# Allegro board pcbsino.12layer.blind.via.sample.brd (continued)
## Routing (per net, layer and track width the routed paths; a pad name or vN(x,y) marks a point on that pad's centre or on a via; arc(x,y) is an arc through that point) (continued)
DDR2_CSN0: length 44.8
  TOP w0.114: U10.L2 7.83,14.71
  TOP w0.12: v8(22.27,27.97) U6.P24 ; 7.83,14.71 v8(7.53,15.01) ; U11.L2 v8(7.53,26.21)
  SIG_L5 w0.094: v8(7.53,26.21) 7.53,25.78 7.53,22.7 7.91,22.33 7.91,15.37 7.54,15.01 v8(7.53,15.01)
  SIG_L8 w0.091: v8(7.53,26.21) 7.53,24.79 7.84,24.47 10.89,24.47 11.17,24.75 11.17,26.53 11.27,26.63 11.48,26.63 11.57,26.54 11.57,25.99 11.66,25.9 11.8,25.9 11.89,25.99 11.89,26.54 11.98,26.63 12.12,26.63 12.21,26.54 12.21,25.99 12.3,25.9 12.44,25.9 12.53,25.99 12.53,26.54 12.62,26.63 12.76,26.63 12.85,26.54 12.85,25.99 12.94,25.9 13.08,25.9 13.17,25.99 13.17,26.54 13.26,26.63 15.95,26.63 16.12,26.8 16.12,27.72 16.25,27.86 16.38,27.86 16.72,27.52 16.85,27.52 16.95,27.61 16.95,27.74 16.61,28.08 16.61,28.21 16.7,28.31 16.83,28.31 17.17,27.97 17.3,27.97 17.4,28.06 17.4,28.19 17.06,28.53 17.06,28.66 17.16,28.76 17.29,28.76 17.63,28.42 17.76,28.42 17.85,28.52 17.85,28.65 17.51,28.99 17.51,29.12 17.62,29.22 17.93,29.22 18.02,29.31 18.02,29.49 18.12,29.58 18.25,29.58 18.34,29.49 18.34,29.31 18.44,29.22 18.57,29.22 18.66,29.31 18.66,29.49 18.76,29.58 18.89,29.58 18.98,29.49 18.98,29.31 19.08,29.22 19.21,29.22 19.3,29.31 19.3,29.49 19.4,29.58 19.53,29.58 19.62,29.49 19.62,29.31 19.72,29.22 19.85,29.22 19.94,29.31 19.94,29.49 20.04,29.58 20.17,29.58 20.26,29.49 20.26,29.27 20.59,28.94 22.18,28.94 22.27,28.85 v8(22.27,27.97)
  BOTTOM w0.114: R102.2 7.55,16.43
  BOTTOM w0.12: 7.55,16.43 7.76,16.22 7.76,15.24 v8(7.53,15.01)
DDR2_D0: length 17
  TOP w0.114: U6.E26 21.05,21.17 20.85,20.97
  TOP w0.12: v2(13.94,10.2) U10.D7 ; 20.85,20.97 v2(20.64,20.76)
  INT_L3 w0.091: v2(13.94,10.2) 13.94,10.1 14.02,10.01
  INT_L3 w0.094: v2(20.64,20.76) 20.69,20.71 20.69,20.18 20.07,19.56 19.72,19.56 19.5,19.34 19.5,18.71 18.69,17.89 18.69,12 16.98,10.3 15.51,10.3 14.85,9.64 14.39,9.64 14.02,10.01
DDR2_D1: length 17
  TOP w0.114: v2(14.72,15) 14.7,15 14.4,14.7 14.4,14.67 U10.C2 ; v2(21.48,22.37) 21.87,22.75 U6.G25
  INT_L3 w0.094: v2(14.72,15) 14.72,15.23 15.1,15.61 15.26,15.61 15.35,15.52 15.35,15.01 15.44,14.92 15.56,14.92 15.65,15.01 15.65,15.52 15.74,15.61 16.17,15.61 16.46,15.9 16.46,16.74 16.38,16.83 15.5,16.83 15.41,16.91 15.41,17.07 15.5,17.16 16.38,17.16 16.46,17.25 16.46,17.4 16.38,17.48 16,17.48 15.92,17.57 15.92,17.7 16,17.79 16.38,17.79 16.46,17.88 16.46,19.28 18.51,21.32 18.79,21.32 19.17,21.7 20.82,21.7 v2(21.48,22.37)
DDR2_D2: length 17
  TOP w0.114: v2(15.5,12.84) 15.5,13.38 U10.A3
  TOP w0.12: v2(22.22,21.58) 22.22,21.6 21.87,21.95 U6.F25
  INT_L3 w0.094: v2(15.5,12.84) 15.5,12.93 15.76,13.19 15.76,13.31 15.62,13.46 15.62,13.58 15.7,13.67 15.83,13.67 15.97,13.52 16.09,13.52 16.18,13.61 16.18,13.73 16.04,13.88 16.04,14 16.12,14.09 16.25,14.09 16.39,13.94 16.51,13.94 16.6,14.03 16.6,14.15 16.46,14.3 16.46,14.42 16.54,14.51 16.67,14.51 16.81,14.36 16.93,14.36 17.02,14.45 17.02,14.57 16.88,14.72 16.88,14.84 16.96,14.93 17.09,14.93 17.23,14.78 17.35,14.78 17.47,14.9 17.47,18.73 17.62,18.88 17.62,19.03 17.47,19.18 17.47,19.37 18.73,20.63 19.21,20.63 19.73,21.15 21.31,21.15 21.31,21.15 21.64,21.15 22.06,21.58 v2(22.22,21.58)
DDR2_D3: length 17
  TOP w0.114: v2(22.62,21.91) 22.62,21.93 U6.F24 ; v2(15.49,9.44) U10.B8
  INT_L3 w0.091: v2(22.62,21.91) 22.62,21.55 22.22,21.15 22.11,21.15 21.86,20.9 21.86,20.79
  INT_L3 w0.094: 21.86,20.79 21.86,20.56 21.69,20.38 21.33,20.38 20.36,19.42 20.36,19.04 18.99,17.67 18.99,11.8 17.11,9.92 15.89,9.92 15.49,9.52 v2(15.49,9.44)
DDR2_D4: length 17
  TOP w0.114: U6.F26 21.43,21.61 v2(21.43,21.55) ; v2(15.52,14.2) U10.A2
  INT_L3 w0.091: 20.31,21.43 19.42,21.43 18.95,20.95 18.62,20.95 17.14,19.47 17.14,19.12 17.05,19.03 16.87,19.03 16.78,18.95 16.78,18.83 16.87,18.74 17.05,18.74 17.14,18.65 17.14,18.53 17.05,18.45 16.87,18.45 16.78,18.36 16.78,18.24 16.87,18.15 17.05,18.15 17.14,18.06 17.14,17.94 17.05,17.86 16.87,17.86 16.78,17.77 16.78,17.65 16.87,17.56 17.05,17.56 17.14,17.47 17.14,17.35 17.05,17.27 16.87,17.27 16.78,17.18 16.78,17.06 16.87,16.97 17.05,16.97 17.14,16.89 17.14,16.76 17.05,16.68 16.87,16.68 16.78,16.59 16.78,16.47 16.87,16.38 17.05,16.38 17.14,16.3 17.14,16.17 17.05,16.09 16.87,16.09 16.78,16 16.78,15.88 16.87,15.79 17.05,15.79 17.14,15.71 17.14,15.38 16.98,15.22 16.65,15.22 16.51,15.36 16.38,15.36 16.3,15.28 16.3,15.16 16.44,15.01 16.44,14.89 16.17,14.62 15.25,14.62 15.16,14.53 15.16,14.29 15.25,14.2 v2(15.52,14.2)
  INT_L3 w0.094: 20.31,21.43 21.3,21.43 v2(21.43,21.55)
DDR2_D5: length 17
  TOP w0.114: v2(14.33,13.14) U10.C3
  TOP w0.12: U6.F27 19.87,21.57 19.01,21.57 18.18,20.74 v2(18.18,19.6)
  INT_L3 w0.091: v2(14.33,13.14) 14.24,13.14 14.11,13.01 14.11,12.79 14.8,12.1 15.23,12.1 16.51,13.38 16.63,13.38 16.93,13.08 17.05,13.08 17.13,13.17 17.13,13.29 16.84,13.59 16.84,13.71 16.92,13.79 17.04,13.79 17.34,13.5 17.46,13.5 17.55,13.58 17.55,13.71 17.25,14 17.25,14.12 17.8,14.67 17.8,18.45 18.18,18.83 v2(18.18,19.6)
DDR2_D6: length 17
  TOP w0.114: U10.A7 16.28,10.96 v2(16.32,10.96)
  TOP w0.12: v2(19.87,20.77) U6.E27
  INT_L3 w0.091: v2(16.32,10.96) 16.5,10.78 16.88,10.78 17.05,10.95 17.05,11.07 16.63,11.5 16.63,11.62 16.71,11.71 16.84,11.71 17.26,11.28 17.38,11.28 17.47,11.37 17.47,11.49 17.04,11.91 17.04,12.04 17.13,12.12 17.25,12.12 17.68,11.7 17.8,11.7 17.88,11.78 17.88,11.91 17.46,12.33 17.46,12.45 17.55,12.54 17.67,12.54 18.09,12.11 18.21,12.11 18.41,12.31 18.41,18.1 19.12,18.81 19.12,20.02 v2(19.87,20.77)
DDR2_D7: length 17
  TOP w0.114: U10.C8 14.48,9.95 14.48,9.95 14.67,10.15 v2(14.67,10.2)
  TOP w0.12: v2(18.58,19.95) 18.58,20.49 19.27,21.17 U6.E28
  INT_L3 w0.091: v2(14.67,10.2) 15.64,11.17 15.64,11.29 15.28,11.65 15.28,11.77 15.37,11.86 15.49,11.86 15.85,11.5 15.97,11.5 16.06,11.58 16.06,11.71 15.7,12.07 15.7,12.19 15.78,12.28 15.91,12.28 16.27,11.92 16.39,11.92 16.48,12 16.48,12.12 16.12,12.48 16.12,12.61 16.2,12.69 16.32,12.69 16.58,12.43 16.91,12.43 18.1,13.63 18.1,18.3 18.58,18.78 v2(18.58,19.95)
DDR2_D8: length 20.5
  TOP w0.12: U10.F8 v8(12.33,9.41) ; v8(23.07,23.17) U6.H23
  SIG_L10 w0.091: v8(12.33,9.41) 12.74,10.4 13,10.66 14.8,10.66 18.58,14.44 18.58,17.98 18.8,18.51 18.96,18.57 19.29,19.37 19.23,19.53 19.46,20.1 22.14,22.77 22.34,22.77 22.9,23 v8(23.07,23.17)
DDR2_D9: length 20.5
  TOP w0.114: v8(11.65,11.19) 11.65,10.88 U10.F7
  TOP w0.12: v8(21.47,23.17) U6.H25
  SIG_L10 w0.091: v8(11.65,11.19) 12.01,11.54 14.09,11.54 14.31,11.77 14.31,11.9 14.2,12.01 14.2,12.14 14.33,12.27 14.46,12.27 14.57,12.15 14.7,12.15 15.69,13.14 15.69,13.27 15.54,13.42 15.54,13.55 15.67,13.68 15.8,13.68 15.95,13.53 16.08,13.53 16.21,13.66 16.21,13.79 16.06,13.94 16.06,14.07 16.19,14.2 16.31,14.2 16.46,14.05 16.59,14.05 16.86,14.31 16.86,19.14 20.52,22.8 21.09,22.8 v8(21.47,23.17)
DDR2_D10: length 20.5
  TOP w0.12: v8(22.27,23.17) U6.H24 ; U10.H8 v8(10.73,9.41)
  SIG_L10 w0.091: v8(22.27,23.17) 21.9,22.99 19.23,20.32 18.18,17.78 18.18,15.76 17.41,13.9 14.47,10.96 12.98,10.96 12.71,10.85 12.19,10.5 10.86,9.41 v8(10.73,9.41)
DDR2_D11: length 20.5
  TOP w0.114: 10.74,14.21 U10.G2
  TOP w0.12: v8(10.73,14.21) 10.74,14.21 ; v8(20.67,23.17) U6.H26
  SIG_L10 w0.091: v8(20.67,23.17) 20.43,23.17 16.45,19.19 16.45,15.41 16.07,15.02 15.69,15.02 15.34,14.67 15.34,14.01 13.31,11.99 11,11.99 10.58,12.41 10.58,14.03 10.7,14.15 10.7,14.17 v8(10.73,14.21)
DDR2_D12: length 20.5
  TOP w0.12: v8(20.67,22.37) U6.G26 ; U10.H7 v8(9.93,10.21)
  SIG_L10 w0.091: v8(9.93,10.21) 11.2,10.21 12.23,11.24 14.24,11.24 17.19,14.19 17.77,15.86 17.77,17.22 17.68,17.31 17.58,17.31 17.49,17.4 17.49,17.58 17.58,17.67 17.68,17.67 17.77,17.77 17.77,17.95 17.68,18.04 17.58,18.04 17.49,18.13 17.49,18.31 17.58,18.41 17.68,18.41 17.77,18.5 17.77,18.68 17.68,18.77 17.61,18.77 17.52,18.86 17.52,19.05 17.61,19.14 17.68,19.14 17.77,19.23 17.77,19.48 v8(20.67,22.37)
DDR2_D13: length 20.5
  TOP w0.114: v8(11.53,15.01) U10.F2
  TOP w0.12: v8(21.47,23.97) U6.J25
  SIG_L10 w0.091: v8(21.47,23.97) 20.79,24.65 17.11,24.65 16.2,23.74 15.7,23.74 15.58,23.86 15.41,23.86 15.28,23.74 15.11,23.74 14.99,23.86 14.82,23.86 14.69,23.74 14.53,23.74 14.4,23.86 14.23,23.86 14.1,23.74 13.94,23.74 13.81,23.86 13.64,23.86 13.51,23.74 13.35,23.74 13.22,23.86 13.05,23.86 12.93,23.74 12.44,23.74 11.9,23.2 11.9,17.36 11.73,17.18 11.73,15.2 v8(11.53,15.01)
DDR2_D14: length 20.5
  TOP w0.114: U10.E3 12.73,13.81 v8(12.33,14.2)
  TOP w0.12: v8(20.67,23.97) U6.J26
  SIG_L10 w0.091: v8(12.33,14.2) 12.79,14.67 12.79,16.14 12.7,16.23 12.7,22.81 13.25,23.36 13.46,23.36 13.55,23.27 13.55,23.11 13.64,23.03 13.76,23.03 13.84,23.11 13.84,23.27 13.93,23.36 14.05,23.36 14.14,23.27 14.14,23.11 14.22,23.03 14.35,23.03 14.43,23.11 14.43,23.27 14.52,23.36 14.64,23.36 14.73,23.27 14.73,23.11 14.81,23.03 14.94,23.03 15.02,23.11 15.02,23.27 15.11,23.36 15.23,23.36 15.32,23.27 15.32,23.11 15.4,23.03 16.04,23.03 17.39,24.37 20.27,24.37 v8(20.67,23.97)
DDR2_D15: length 20.5
  TOP w0.12: v8(22.27,23.97) U6.J24 ; v8(11.17,12.61) 11.07,12.61 10.67,13.01 U10.H3
  SIG_L10 w0.091: v8(11.17,12.61) 11.45,12.33 13,12.33 14.11,13.45 14.11,14.36 15.59,15.84 15.59,18.81 15.69,19.07 20.17,23.55 21.84,23.55 v8(22.27,23.97)
DDR2_D16: length 14.8
  TOP w0.114: U11.C2 v8(14.73,26.21)
  TOP w0.12: v8(23.87,25.57) U6.L22
  SIG_L5 w0.091: v8(23.87,25.57) 23.87,25.84 22.98,26.73 22.04,26.73 21.68,27.09 16.86,27.09 16.22,27.72 13.83,27.72 13.53,27.42 13.53,26.7 13.62,26.61 14.33,26.61 v8(14.73,26.21)
DDR2_D17: length 14.8
  TOP w0.12: U11.C8 v8(14.73,20.61) ; v8(25.47,24.77) U6.K20
  SIG_L5 w0.091: v8(25.47,24.77) 25.04,24.35 24.51,24.35 24.29,24.13 24.29,23.81 24.04,23.55 23.68,23.55 23.49,23.36 23.49,23.07 23.18,22.75 23.01,22.75 22.64,22.39 22.64,22.22 22.42,22 22.26,22 21.96,21.7 20.87,21.7 20.15,20.98 19.28,20.98 19.11,20.82 18.98,20.82 18.82,20.98 18.69,20.98 18.52,20.82 18.4,20.82 18.23,20.98 18.1,20.98 17.93,20.82 17.81,20.82 17.64,20.98 17.51,20.98 17.34,20.82 17.22,20.82 17.05,20.98 16.92,20.98 16.75,20.82 16.63,20.82 16.46,20.98 15.11,20.98 v8(14.73,20.61)
DDR2_D18: length 14.7
  TOP w0.114: v8(13.2,22.44) 13.53,22.11 U11.D7
  TOP w0.12: v8(24.67,24.77) U6.K21
  SIG_L5 w0.091: v8(13.2,22.44) 14.04,21.6 20.21,21.6 20.6,22 21.29,22 22.09,22.8 22.42,22.8 22.64,23.02 22.64,23.28 22.91,23.55 23.18,23.55 23.44,23.82 23.44,24.02 23.82,24.4 24.02,24.4 24.4,24.77 v8(24.67,24.77)
DDR2_D19: length 14.8
  TOP w0.114: U11.A2 15.93,25.81 v8(15.53,25.41)
  TOP w0.12: v8(23.07,25.57) U6.L23
  SIG_L5 w0.091: v8(15.53,25.41) 15.34,25.41 15.11,25.64 15.11,27.33 15.22,27.45 15.99,27.45 16.65,26.78 20.53,26.78 20.61,26.7 20.61,26.44 20.7,26.35 20.82,26.35 20.91,26.44 20.91,26.7 21,26.78 21.21,26.78 21.3,26.7 21.3,26.06 21.38,25.97 21.5,25.97 21.59,26.06 21.59,26.34 21.68,26.43 21.8,26.43 21.89,26.34 21.89,26.06 21.97,25.97 22.09,25.97 22.18,26.06 22.18,26.34 22.27,26.43 22.39,26.43 22.47,26.34 22.47,26.06 22.56,25.97 22.95,25.97 23.07,25.86 v8(23.07,25.57)
DDR2_D20: length 14.8
  TOP w0.114: U11.C3 v8(13.93,25.41)
  TOP w0.12: v8(22.27,25.57) U6.L24
  SIG_L5 w0.091: v8(22.27,25.57) 21.02,25.57 20.65,25.94 20.52,25.94 20.26,25.68 20.14,25.68 20.06,25.77 20.06,25.89 20.32,26.15 20.32,26.27 20.13,26.45 19.54,26.45 19.46,26.37 19.46,26.29 19.37,26.2 19.25,26.2 19.16,26.29 19.16,26.37 19.07,26.45 18.95,26.45 18.87,26.37 18.87,26.29 18.78,26.2 18.66,26.2 18.57,26.29 18.57,26.37 18.49,26.45 18.36,26.45 18.28,26.37 18.28,26.29 18.19,26.2 18.07,26.2 17.98,26.29 17.98,26.37 17.9,26.45 17.77,26.45 17.69,26.37 17.69,26.29 17.6,26.2 17.48,26.2 17.39,26.29 17.39,26.37 17.31,26.45 17.18,26.45 17.1,26.37 17.1,26.29 16.82,26.01 16.46,26.01 16.37,26.1 16.37,26.61 16.27,26.71 16.07,26.71 15.97,26.61 15.97,25.16 15.77,24.96 14,24.96 13.91,25.05 13.91,25.39 v8(13.93,25.41)
DDR2_D21: length 14.8
  TOP w0.114: U11.A7 16.15,21.81 v8(16.76,22.42)
  TOP w0.12: v8(23.07,23.97) U6.J23
  SIG_L5 w0.091: v8(16.76,22.42) 17.04,22.7 17.26,22.7 17.35,22.61 17.35,22.15 17.44,22.06 17.56,22.06 17.64,22.15 17.64,22.69 17.73,22.77 17.85,22.77 17.94,22.69 17.94,22.15 18.02,22.06 18.15,22.06 18.23,22.15 18.23,22.69 18.32,22.77 18.44,22.77 18.53,22.69 18.53,22.15 18.61,22.06 18.74,22.06 18.82,22.15 18.82,22.69 18.91,22.77 19.03,22.77 19.12,22.69 19.12,22.15 19.2,22.06 19.33,22.06 19.41,22.15 19.41,22.69 19.5,22.77 19.62,22.77 19.71,22.69 19.71,22.15 19.79,22.06 19.91,22.06 20,22.15 20,22.69 20.09,22.77 21.61,22.77 21.89,23.06 21.89,23.33 22.11,23.55 22.39,23.55 22.68,23.84 22.93,23.84 v8(23.07,23.97)
DDR2_D22: length 14.8
  TOP w0.114: 15.89,25.01 U11.A3
  TOP w0.12: v8(23.87,24.77) U6.K22 ; 15.89,25.01 15.41,24.52 v8(15.41,24.51)
  SIG_L5 w0.091: v8(15.41,24.51) 15.86,24.51 17.2,25.86 19.1,25.86 19.8,25.16 19.95,25.16 20.03,25.07 20.03,24.53 20.12,24.45 20.24,24.45 20.33,24.53 20.33,25.07 20.41,25.16 20.54,25.16 20.62,25.07 20.62,24.53 20.71,24.45 20.83,24.45 20.92,24.53 20.92,25.07 21,25.16 21.12,25.16 21.21,25.07 21.21,24.53 21.3,24.45 21.42,24.45 21.51,24.53 21.51,25.07 21.59,25.16 21.83,25.16 21.92,25.07 21.92,24.99 22,24.91 22.13,24.91 22.21,24.99 22.21,25.07 22.3,25.16 23.54,25.16 23.87,24.83 v8(23.87,24.77)
DDR2_D23: length 14.8
  TOP w0.114: U11.B8 v8(15.53,20.61)
  TOP w0.12: v8(25.47,23.97) U6.J20
  SIG_L5 w0.091: v8(25.47,23.97) 25.47,23.89 25.13,23.55 24.51,23.55 24.25,23.28 24.25,22.9 24.1,22.75 23.71,22.75 23.49,22.53 23.49,22.19 23.3,22 22.89,22 22.29,21.4 21.05,21.4 20.08,20.43 19.5,20.43 19.24,20.18 18.85,20.18 18.77,20.27 18.77,20.32 18.68,20.41 18.56,20.41 18.47,20.32 18.47,20.27 18.39,20.18 18.26,20.18 18.18,20.27 18.18,20.32 18.09,20.41 17.97,20.41 17.88,20.32 17.88,20.27 17.8,20.18 17.67,20.18 17.59,20.27 17.59,20.32 17.5,20.41 17.38,20.41 17.29,20.32 17.29,20.27 17.21,20.18 17.09,20.18 17,20.27 17,20.32 16.91,20.41 16.79,20.41 16.7,20.32 16.7,20.27 16.62,20.18 16.5,20.18 16.41,20.27 16.41,20.32 16.32,20.41 16.2,20.41 16.12,20.32 16.12,20.27 16.03,20.18 15.62,20.18 15.53,20.27 v8(15.53,20.61)
DDR2_D24: length 15.9
  TOP w0.114: U11.F7 11.96,22.67 v2(11.98,22.7)
  INT_L3 w0.091: v2(11.98,22.7) 11.26,22.7 11.17,22.6 11.17,22.46 11.25,22.38 11.51,22.38 11.6,22.29 11.6,22.17 11.51,22.08 11.25,22.08 11.17,21.99 11.17,21.19 11.26,21.1 11.5,21.1 11.65,21.25 11.65,21.65 12.43,22.43 12.43,22.88 12.52,22.96 15.66,22.96 16.52,23.82 16.67,23.97 16.67,24.67 17.46,25.46 19.47,25.46 19.98,25.97 v2(20.26,25.97)
DDR2_D25: length 15.9
  TOP w0.114: U11.H8 v2(10.74,20.61)
  TOP w0.12: v2(20.69,25.64) 21.02,25.97 U6.L26
  INT_L3 w0.091: v2(20.69,25.64) 20.18,25.64 19.19,24.65 17.39,24.65 16.96,24.22 16.96,23.61 15.33,21.98 12.41,21.98 11.96,21.53 11.96,21.14 11.95,21.14 11.95,19.67 11.71,19.43 11.33,19.43 11.12,19.65 11.12,20.23 v2(10.74,20.61)
DDR2_D26: length 15.9
  TOP w0.114: v2(21.4,25.54) 21.4,25.59 21.79,25.97 U6.L25 ; v2(12.33,20.61) U11.F8
  INT_L3 w0.091: v2(12.33,20.61) 12.33,21.5 12.54,21.7 13.62,21.7 13.71,21.62 13.71,21.51 13.79,21.43 13.92,21.43 14,21.51 14,21.62 14.09,21.7 14.21,21.7 14.3,21.62 14.3,21.51 14.38,21.43 14.51,21.43 14.59,21.51 14.59,21.62 14.68,21.7 14.8,21.7 14.89,21.62 14.89,21.51 14.97,21.43 15.09,21.43 15.18,21.51 15.18,21.62 15.27,21.7 15.42,21.7 15.64,21.93 15.76,21.93 16.05,21.63 16.18,21.63 16.26,21.72 16.26,21.84 15.97,22.13 15.97,22.26 17.24,23.53 17.24,24.12 17.49,24.37 19.32,24.37 20.03,25.08 20.18,25.08 20.26,25 20.26,24.77 20.35,24.68 20.47,24.68 20.56,24.77 20.56,25 20.65,25.08 20.95,25.08 v2(21.4,25.54)
DDR2_D27: length 15.9
  TOP w0.114: v2(17.62,25.83) 17.62,25.81 17.74,25.69 17.9,25.69 18.18,25.97 19.07,25.97 U6.L28 ; U11.H7 10.06,22.06 v2(10.05,22.29)
  INT_L3 w0.091: v2(10.05,22.29) 10.05,23.15 10.15,23.25 10.34,23.25 10.43,23.16 10.43,21.97 10.52,21.88 10.66,21.88 10.76,21.98 10.76,23.17 10.85,23.25 11.03,23.25 11.19,23.1 11.33,23.1 11.48,23.25 11.62,23.25 11.78,23.1 11.92,23.1 12.07,23.25 13,23.25 13.15,23.41 13.29,23.41 13.44,23.25 13.59,23.25 13.74,23.41 13.88,23.41 14.03,23.25 14.17,23.25 14.33,23.41 14.47,23.41 14.62,23.25 14.76,23.25 14.92,23.41 15.06,23.41 15.21,23.25 15.59,23.25 16.41,24.08 16.41,24.79 17.45,25.83 v2(17.62,25.83)
DDR2_D28: length 15.9
  TOP w0.114: U11.H3 v2(10.7,25.45) ; v2(23.43,26.72) 23.43,26.74 U6.M23
  INT_L3 w0.091: v2(23.43,26.72) 22.99,26.72 22.69,27.02 22.69,27.3 22.39,27.6 18.74,27.6 18.33,28 11.98,28 11.12,27.14 11.12,25.87 10.7,25.45 v2(10.7,25.45)
DDR2_D29: length 15.9
  TOP w0.114: v2(23.03,26.33) 22.67,26.69 U6.M24 ; v2(11.52,25.44) 11.5,25.44 U11.G2
  INT_L3 w0.091: v2(11.52,25.44) 11.65,25.44 11.8,25.59 11.8,26.17 11.72,26.25 11.51,26.25 11.42,26.34 11.42,26.46 11.51,26.55 11.84,26.55 11.93,26.63 11.93,27.55 12.11,27.73 18.15,27.73 18.54,27.34 21.53,27.34 22.14,26.73 22.47,26.73 22.88,26.33 v2(23.03,26.33)
DDR2_D30: length 15.9
  TOP w0.114: U11.F2 v2(12.29,26.15) ; v2(22.27,26.33) 22.27,26.37 U6.M25
  INT_L3 w0.091: v2(12.29,26.15) 12.46,26.15 12.74,26.43 12.74,27.19 13.02,27.47 14.16,27.47 14.32,27.32 14.32,26.68 14.42,26.58 15.03,26.58 15.13,26.69 15.13,27.37 15.23,27.47 15.98,27.47 16.07,27.38 16.07,27.15 16.16,27.06 16.28,27.06 16.37,27.15 16.37,27.38 16.45,27.47 16.57,27.47 16.66,27.38 16.66,27.15 16.75,27.06 16.87,27.06 16.95,27.15 16.95,27.38 17.04,27.47 17.16,27.47 17.25,27.38 17.25,27.15 17.34,27.06 17.46,27.06 17.54,27.15 17.54,27.38 17.63,27.47 18,27.47 18.41,27.06 21.35,27.06 22.09,26.33 v2(22.27,26.33)
DDR2_D31: length 15.9
  TOP w0.114: U11.E3 v2(12.36,25.38) ; U6.M26 21.48,26.36 v2(21.48,26.33)
  INT_L3 w0.091: v2(21.48,26.33) 21.48,26.51 21.2,26.78 21.02,26.78 20.94,26.7 20.94,26.11 20.85,26.02 20.73,26.02 20.64,26.11 20.64,26.7 20.56,26.78 16.88,26.78 15.92,25.82 15.41,25.82 15.15,25.56 15.15,24.8 15,24.65 14.7,24.65 14.62,24.73 14.62,24.96 14.34,25.24 14.34,25.72 14.24,25.82 13.55,25.82 13.47,25.91 13.47,26.52 13.38,26.61 13.26,26.61 13.17,26.52 13.17,25.91 13.09,25.82 12.45,25.82 12.36,25.73 v2(12.36,25.38)
DDR2_DQM0: length 17
  TOP w0.114: v2(13.83,13.3) 13.53,13.6 U10.D3
  TOP w0.12: U6.F28 19.4,21.91 18.66,21.91 v2(18.44,21.69)
  INT_L3 w0.091: v2(13.83,13.3) 13.66,13.48 13.66,13.75 13.74,13.84 13.95,13.84 14.04,13.92 14.04,14.05 13.95,14.13 13.74,14.13 13.66,14.22 13.66,14.34 13.74,14.43 13.95,14.43 14.04,14.51 14.04,14.64 13.95,14.72 13.74,14.72 13.66,14.81 13.66,14.93 13.74,15.02 13.95,15.02 14.04,15.1 14.04,15.23 13.95,15.31 13.74,15.31 13.66,15.4 13.66,15.52 13.74,15.61 13.95,15.61 14.04,15.69 14.04,15.81 13.95,15.9 13.74,15.9 13.66,15.99 13.66,16.27 13.83,16.44 13.95,16.44 14.11,16.28 14.23,16.28 14.31,16.37 14.31,16.49 14.16,16.65 14.16,16.77 14.24,16.86 14.37,16.86 14.52,16.7 14.65,16.7 14.73,16.78 14.73,16.91 14.57,17.06 14.57,17.19 14.66,17.27 14.78,17.27 14.94,17.12 15.06,17.12 15.15,17.2 15.15,17.32 14.99,17.48 14.99,17.6 15.08,17.69 15.2,17.69 15.36,17.53 15.48,17.53 15.57,17.62 15.57,17.74 15.41,17.9 15.41,18.02 15.49,18.11 15.8,18.11 16.1,18.4 16.1,19.34 v2(18.44,21.69)
DDR2_DQM1: length 20.5
  TOP w0.12: v8(22.27,22.37) U6.G24 ; U10.E7 v8(13.13,10.21)
  SIG_L10 w0.091: v8(13.13,10.21) 15.16,10.21 15.4,10.44 15.53,10.44 15.61,10.35 15.74,10.35 15.87,10.48 15.87,10.61 15.79,10.7 15.79,10.83 15.92,10.96 16.05,10.96 16.13,10.87 16.26,10.87 16.39,11 16.39,11.13 16.3,11.22 16.3,11.35 16.43,11.48 16.56,11.48 16.65,11.39 16.78,11.39 16.91,11.52 16.91,11.65 16.82,11.73 16.82,11.86 16.95,11.99 17.08,11.99 17.17,11.91 17.3,11.91 17.43,12.04 17.43,12.17 17.34,12.25 17.34,12.38 17.47,12.51 17.6,12.51 17.68,12.42 17.81,12.42 17.94,12.55 17.94,12.68 17.86,12.77 17.86,12.9 18.08,13.12 18.46,13.12 19.02,13.68 19.02,17.64 20.67,19.29 20.67,20.77 v8(22.27,22.37)
DDR2_DQM2: length 14.8
  TOP w0.12: v8(23.07,24.77) U6.K23 ; U11.D3 v8(13.13,25.41)
  SIG_L5 w0.091: v8(23.07,24.77) 22.74,24.45 22.14,24.45 21.86,24.17 21.86,23.83 21.58,23.55 19.78,23.55 19.5,23.82 19.5,25.08 19.04,25.54 17.37,25.54 15.92,24.09 13.96,24.09 13.13,24.93 v8(13.13,25.41)
DDR2_DQM3: length 15.9
  TOP w0.114: U11.E7 12.73,21.79 v2(13.12,21.4) ; U6.M22 v2(23.89,26.35)
  INT_L3 w0.091: 13.14,21.4 13.14,21.18 13.28,21.04 13.5,21.04 13.58,20.96 13.58,20.77 13.67,20.69 13.79,20.69 13.88,20.77 13.88,20.96 13.96,21.04 16.1,21.04 17.37,22.31 17.37,22.8 17.95,23.38 19.14,23.38 19.5,23.74 19.5,24.09 19.5,24.14 19.79,24.42 21.38,24.42 22.15,25.2 23.22,25.2 23.44,25.42 23.44,26.18 23.61,26.35 v2(23.89,26.35) ; 13.14,21.4 v2(13.12,21.4) ; 13.14,21.4 13.13,21.41
DDR2_DQS0_N: length 17
  TOP w0.102: U10.B7 14.9,10.83 v2(14.9,11.11)
  TOP w0.114: v2(20.22,22.8) 20.24,22.8 U6.G27
  INT_L3 w0.089: v2(20.22,22.8) 20.08,22.8 19.99,22.71 20,22.57 20,22.28 19.77,22.05 18.1,22.05 15.6,19.55 15.6,18.79 13.26,16.45 13.26,13.09 14.8,11.56 14.8,11.21 v2(14.9,11.11)
DDR2_DQS0_P: length 17
  TOP w0.102: U10.C7 14.58,10.86 14.58,11 v2(14.5,11.09)
  TOP w0.114: U6.G28 v2(19.52,22.77)
  INT_L3 w0.089: v2(19.52,22.77) 19.66,22.78 19.75,22.69 19.76,22.57 19.76,22.38 19.67,22.29 18,22.29 15.36,19.65 15.36,18.89 13.02,16.55 13.02,12.99 14.56,11.46 14.56,11.2 v2(14.5,11.09)
DDR2_DQS1_N: length 20.5
  TOP w0.102: v8(18.46,23.79) 18.31,23.79 18.13,23.61 18.13,23.36 18.26,23.23 18.97,23.23 19.31,23.57 U6.H28 ; v8(11.63,13.31) U10.G3
  SIG_L10 w0.089: v8(11.63,13.31) 11.74,13.31 12.31,12.74 12.73,12.74 13.47,13.48 13.47,15.15 13.96,15.65 13.96,16.31 13.73,16.54 13.56,16.54 13.47,16.63 13.47,16.8 13.56,16.89 13.73,16.89 13.96,17.12 13.96,17.58 13.47,18.07 13.47,19 14.04,19.57 14.04,21.24 14.32,21.51 17.36,21.51 18.22,22.37 18.22,23.53 v8(18.46,23.79)
DDR2_DQS1_P: length 20.5
  TOP w0.102: v8(12.29,13.32) 12.29,13.45 U10.F3 ; v8(17.77,23.76) 17.87,23.66 17.87,23.25 18.15,22.97 19.07,22.97 19.29,23.19 19.71,23.19 20.1,23.57 U6.H27
  SIG_L10 w0.089: v8(12.29,13.32) 12.31,13.3 12.31,13.08 12.41,12.98 12.63,12.98 13.23,13.58 13.23,15.25 13.72,15.75 13.72,16.21 13.63,16.3 13.46,16.3 13.23,16.53 13.23,16.9 13.46,17.13 13.63,17.13 13.72,17.22 13.72,17.48 13.23,17.97 13.23,19.1 13.8,19.67 13.8,21.34 14.22,21.76 17.26,21.76 17.97,22.47 17.97,23.57 v8(17.77,23.76)
DDR2_DQS2_N: length 14.7
  TOP w0.102: v8(18.61,25.08) 18.61,24.47 18.71,24.37 19.02,24.37 19.1,24.45 19.1,25.23 19.18,25.31 19.33,25.31 19.42,25.22 19.42,25.22 U6.K28 ; v8(15.09,22.4) 14.95,22.4 14.83,22.28 14.83,21.99 15,21.81 U11.B7
  SIG_L5 w0.089: v8(18.61,25.08) 18.41,24.89 18.41,24.66 18.09,24.33 17.19,24.33 17.1,24.24 17.1,23.75 16.87,23.52 16.34,23.52 16.25,23.44 16.25,22.62 16.02,22.39 15.7,22.39 15.48,22.62 15.48,23.44 15.39,23.52 13.17,23.52 13.09,23.43 13.09,23.23 13.17,23.14 14.7,23.14 14.88,22.96 14.88,22.52 14.99,22.4 v8(15.09,22.4)
DDR2_DQS2_P: length 14.8
  TOP w0.102: v8(17.97,25.08) 17.97,25.25 18.29,25.57 19.88,25.57 U6.K27 ; v8(14.47,22.42) 14.57,22.31 14.57,22.03 14.35,21.81 U11.C7
  SIG_L5 w0.089: v8(14.47,22.42) 14.63,22.58 14.63,22.86 14.6,22.9 13.07,22.9 12.84,23.13 12.84,23.53 13.07,23.76 15.49,23.76 15.72,23.54 15.72,22.72 15.8,22.63 15.92,22.63 16.01,22.72 16.01,23.54 16.24,23.76 16.77,23.76 16.86,23.85 16.86,24.34 17.09,24.57 17.99,24.57 18.17,24.76 18.17,24.89 v8(17.97,25.08)
DDR2_DQS3_N: length 15.9
  TOP w0.102: U6.M27 19.88,26.41 v2(19.88,26.35)
  INT_L3 w0.089: v2(19.88,26.35) 19.64,26.11 19.37,25.86 18.59,25.86 18.24,26.2 17.27,26.2 16.09,25.02 16.09,24.21 15.69,23.8 14.13,23.8 13.9,24.03 13.9,24.6 13.82,24.69 13.7,24.69 13.61,24.6 13.61,24.03 13.39,23.8 13.06,23.8 12.84,24.03 12.84,24.6 12.75,24.69 12.63,24.69 12.55,24.6 12.55,23.95 12.26,23.66 10.92,23.66 10.69,23.89 10.69,24.41 11.14,24.87 11.14,24.98 v2(11.12,25.01)
DDR2_DQS3_P: length 15.9
  TOP w0.102: v2(19.02,26.43) 19.26,26.75 U6.M28
  INT_L3 w0.089: v2(19.02,26.43) 19.32,26.43 19.41,26.34 19.41,26.23 19.28,26.1 18.69,26.1 18.34,26.44 17.17,26.44 15.85,25.12 15.85,24.31 15.59,24.04 14.23,24.04 14.15,24.13 14.15,24.7 13.92,24.93 13.6,24.93 13.37,24.7 13.37,24.13 13.29,24.04 13.16,24.04 13.08,24.13 13.08,24.7 12.85,24.93 12.53,24.93 12.3,24.7 12.3,24.05 12.16,23.9 11.02,23.9 10.93,23.99 10.93,24.31 11.62,25.01 v2(11.93,25.01)
DDR2_ODT0: length 44.9
  TOP w0.114: U11.K1 v8(9.12,27) ; U6.R23 23.47,29.22 v8(23.11,29.58) ; U10.K1 8.63,15.51
  TOP w0.12: 8.63,15.51 v8(8.33,15.81)
  INT_L3 w0.091: v8(9.12,27) 8.73,26.61
  INT_L3 w0.094: v8(8.33,15.81) 8.73,16.21 8.73,26.61
  SIG_L8 w0.091: v8(23.11,29.58) 23.23,29.58 23.49,29.83 23.49,30.57 23.28,30.77 21.99,30.77 21.18,31.59 18.25,31.59 16.76,30.09 15.61,30.09 15.52,30 15.52,29.42 15.42,29.32 15.29,29.32 15.2,29.42 15.2,30 15.1,30.09 14.97,30.09 14.88,30 14.88,29.42 14.78,29.32 14.65,29.32 14.56,29.42 14.56,30 14.46,30.09 14.33,30.09 14.24,30 14.24,29.42 14.14,29.32 14.01,29.32 13.92,29.42 13.92,30 13.82,30.09 13.69,30.09 13.6,30 13.6,29.42 13.5,29.32 13.37,29.32 13.28,29.42 13.28,30 13.18,30.09 13.05,30.09 12.96,30 12.96,29.42 12.86,29.32 12.73,29.32 12.64,29.42 12.64,30 12.54,30.09 12.41,30.09 12.32,30 12.32,29.42 12.22,29.32 12.09,29.32 12,29.42 12,30 11.9,30.09 11.77,30.09 11.68,30 11.68,29.42 11.58,29.32 11.45,29.32 11.36,29.42 11.36,30 11.26,30.09 11.13,30.09 11.04,30 11.04,29.42 10.94,29.32 10.81,29.32 10.72,29.42 10.72,30 10.62,30.09 10.49,30.09 10.4,30 10.4,29.42 10.3,29.32 10.17,29.32 10.08,29.42 10.08,29.87 9.98,29.96 9.39,29.96 9.16,29.73 9.16,27.04 v8(9.12,27)
  BOTTOM w0.114: R125.2 8.35,16.42 8.33,16.4
  BOTTOM w0.12: 8.33,16.4 v8(8.33,15.81)
DDR2_RASN: length 44.9
  TOP w0.114: U6.T23 v8(23.08,30.37) ; U10.J3 9.43,13.91 ; v8(9.14,25.39) 9.13,25.41 U11.J3
  TOP w0.12: 9.43,13.91 v8(9.13,14.21)
  INT_L3 w0.091: 23.14,30.3 v8(23.08,30.37)
  INT_L3 w0.094: v8(9.13,14.21) 9.52,14.59 9.52,25.01 v8(9.14,25.39)
  SIG_L8 w0.091: v8(23.08,30.37) 22.62,29.91 22.17,29.91 21.63,30.44 20.54,30.44 20.16,30.82 18.2,30.82 16.3,28.92 15.44,28.92 15.35,28.83 15.35,28.12 15.26,28.03 15.12,28.03 15.03,28.12 15.03,28.83 14.94,28.92 14.8,28.92 14.71,28.83 14.71,28.12 14.62,28.03 14.48,28.03 14.39,28.12 14.39,28.83 14.3,28.92 14.16,28.92 14.07,28.83 14.07,28.12 13.98,28.03 13.84,28.03 13.75,28.12 13.75,28.83 13.66,28.92 13.52,28.92 13.43,28.83 13.43,28.12 13.34,28.03 13.2,28.03 13.11,28.12 13.11,28.83 13.02,28.92 12.88,28.92 12.79,28.83 12.79,28.12 12.7,28.03 12.56,28.03 12.47,28.12 12.47,28.83 12.38,28.92 12.24,28.92 12.15,28.83 12.15,28.12 12.06,28.03 11.92,28.03 11.83,28.12 11.83,28.83 11.74,28.92 11.6,28.92 11.51,28.83 11.51,28.12 11.42,28.03 11.28,28.03 11.19,28.12 11.19,28.83 11.1,28.92 10.96,28.92 10.87,28.83 10.87,28.12 10.78,28.03 10.64,28.03 10.55,28.12 10.55,28.83 10.46,28.92 10,28.92 9.82,28.74 9.82,25.79 9.42,25.39 v8(9.14,25.39)
  BOTTOM w0.114: v8(9.13,14.21) 9.21,14.12 R103.2
DDR2_RST: length 43.6
  TOP w0.114: U6.R24 22.62,29.17 v2(22.29,29.5) ; U11.T2 v8(3.53,26.21) ; U10.T2 3.93,14.61
  TOP w0.12: 3.93,14.61 v8(3.53,15.01)
  INT_L3 w0.091: v8(3.53,26.21) 2.55,26.21 2,26.76 2,31.13 2.28,31.41 20.06,31.41 20.19,31.54 21.22,31.54 22.01,30.75 22.49,30.75 22.67,30.57 22.67,29.88 v2(22.29,29.5)
  SIG_L5 w0.094: v8(3.53,15.01) 3.51,15.02 3.51,19.82 3.9,20.21 3.9,23.89 3.13,24.66 3.13,25.81 v8(3.53,26.21)
  BOTTOM w0.114: R128.1 3.53,16.37 v8(3.53,15.01)
DDR2_WEN: length 44.9
  TOP w0.114: U6.U25 21.53,30.44 v2(21.53,30.37) ; v2(7.54,25.41) 7.53,25.41 U11.L3
  TOP w0.12: U10.L3 v8(7.53,14.21)
  INT_L3 w0.091: v2(7.54,25.41) 7.15,25.8 7.15,26.86 7.38,27.08 7.38,28.76 7.84,29.22 9.06,29.22 9.15,29.14 9.15,28.67 9.23,28.59 9.36,28.59 9.44,28.67 9.44,29.14 9.53,29.22 9.74,29.22 9.82,29.14 9.82,27.61 9.91,27.52 10.07,27.52 10.15,27.61 10.15,29.14 10.24,29.22 18.33,29.22 18.74,28.81 18.74,28.61 18.96,28.39 19.27,28.39 19.32,28.44 19.62,28.44 19.7,28.52 19.7,28.96 19.79,29.05 19.91,29.05 20,28.96 20,28.52 20.09,28.44 20.21,28.44 20.29,28.52 20.29,29.04 20.38,29.12 20.5,29.12 20.59,29.04 20.59,28.52 20.67,28.44 20.8,28.44 20.88,28.52 20.88,29.04 20.97,29.12 21.09,29.12 21.18,29.04 21.18,28.52 21.26,28.44 23.16,28.44 23.28,28.56 23.28,28.97 23.21,29.05 21.94,29.05 21.78,29.2 21.78,30.11 v2(21.53,30.37)
  INT_L3 w0.094: v2(7.54,25.41) 7.37,25.25 7.37,25.25 7.16,25.04 7.16,21.57 7.15,21.56 7.15,19.53 7.16,19.52 7.16,19.21 7.15,19.2 7.15,14.58 v8(7.53,14.21)
  BOTTOM w0.114: v8(7.53,14.21) 7.61,14.12 R105.2
DDR_VREF_OFFN: length 100.9
  TOP w0.12: v2(23.72,18.38) 24.12,17.97 U6.A22
  INT_L3 w0.091: v2(14.09,66.26) 13.99,66.15 v3(13.5,66.15) ; v3(23.64,17.72) 23.64,18.3 v2(23.72,18.38)
  SIG_L5 w0.091: v3(13.5,66.15) 9.92,66.15 7.54,63.77 7.54,58.76 1.03,52.26 1.03,15.38 2.16,14.25 2.16,7.24 3.52,5.88 16.15,5.88 18.84,8.57 18.84,17.39 19.32,17.87 23.49,17.87 v3(23.64,17.72)
EEPROM_A0(NC): length 3.2
  BOTTOM w0.114: U16.1 24.7,1.37 R226.1 R231.1
EEPROM_A1(NC): length 3
  BOTTOM w0.114: U16.2 R233.1 R232.1
EEPROM_A2: length 3.2
  BOTTOM w0.114: R235.1 R236.1 24.82,3.91 U16.3
EMAC[0]_RXC/PHYAD1: length 14.7
  TOP w0.114: v2(44.9,33.08) 44.82,33.08 44.31,33.6 R286.1 45.2,33.74 45.49,33.46 R285.2 C177.1 46.38,33.46 46.78,33.06 46.78,32.83 47.12,32.49 U17.28
  INT_L3 w0.091: v2(44.9,33.08) 44.6,33.38 44.23,33.38 44.1,33.25 44.1,32.66 44.02,32.58 43.9,32.58 43.82,32.66 43.82,33.18 43.74,33.26 43.63,33.26 43.55,33.18 43.55,32.66 43.47,32.58 43.36,32.58 43.27,32.66 43.27,33.18 43.19,33.26 43.08,33.26 43,33.18 43,32.66 42.92,32.58 42.81,32.58 42.73,32.66 42.73,32.9 42.65,32.98 42.13,32.98 42.02,32.88 42.02,32.04 41.88,31.89 v3(41.44,31.89)
  SIG_L10 w0.091: v3(41.44,31.89) 41.44,31.46 v5(41.35,31.37)
  BOTTOM w0.114: v5(41.35,31.37) 41.03,31.05 R260.2
EMAC[0]_RXCTL/PHYAD2: length 15.6
  TOP w0.114: U17.27 47.28,32.89 47.08,33.09 47.08,33.9 46.52,34.46 46.35,34.46 R287.2 R288.1 45.31,34.26 v2(45.22,34.16)
  INT_L3 w0.091: v2(45.22,34.16) 45.36,34.02 45.51,34.02 45.59,34.1 45.59,34.45 45.67,34.53 45.87,34.53 45.97,34.44 45.97,34.12 46.06,34.02 46.25,34.02 46.35,34.13 46.35,34.48 46.06,34.77 44.88,34.77 44.72,34.62 44.72,34.35 44.53,34.16 44.42,34.16 44.01,34.57 43.9,34.57 43.82,34.49 43.82,34.38 44.22,33.97 44.22,33.86 44.12,33.76 44.01,33.76 43.92,33.85 43.8,33.85 43.72,33.77 43.72,33.63 43.64,33.54 42.94,33.54 42.71,33.31 41.73,33.31 41.65,33.31 v3(41.55,33.21)
  SIG_L10 w0.091: v3(41.55,33.21) 41.52,33.21 40.78,32.47 40.78,32.07 v5(40.86,31.99)
EMAC[0]_RXD0/RXDLY: length 8.7
  TOP w0.114: U17.26 48.37,33.29 47.52,33.29 47.34,33.46 47.34,34.03 47.44,34.13 47.54,34.13 47.64,34.23 47.64,34.48 47.46,34.66 47.32,34.66 47.08,34.42 46.94,34.42 46.84,34.53 46.84,34.67 47.07,34.91 47.07,35.05 46.4,35.72 45.27,35.72 45.15,35.83 45.15,36.37 45.1,36.43 R278.2 44.29,36.44 R267.2 44.09,36.23 44.09,35.73 R279.1
EMAC[0]_RXD1/CFG_MODE0: length 8.7
  TOP w0.114: R261.2 R280.2 44.67,37.67 44.67,37.94 44.77,38.04 45.36,38.04 45.61,37.78 46.32,37.78 46.42,37.71 46.5,37.63 46.5,36.05 46.9,35.64 46.91,35.64 47.92,34.63 47.92,33.8 48.03,33.69 U17.25
EMAC[0]_RXD2/CFG_MODE1: length 6.4
  TOP w0.114: U17.24 49.13,34.98 48.79,35.32 48.1,35.32 47.38,36.04 47.38,36.88 46.98,37.29 R281.2 46.9,37.71 46.47,38.08 45.89,38.08 R262.2
EMAC[0]_RXD3/CFG_MODE2: length 5
  TOP w0.114: R263.2 R282.2 47.83,37.29 48.28,36.85 48.28,35.95 48.61,35.62 48.91,35.62 49.53,35.01 U17.23
EMAC[0]_TXC: length 21.1
  TOP w0.114: v2(48.63,37.83) 48.63,37.45 R268.1 ; v2(35.07,32.78) 34.67,32.38 U6.W9
  INT_L3 w0.091: v2(48.63,37.83) 48.07,38.39 47.52,38.39 47.03,38.88 46.3,38.88 46.22,38.79 46.22,38.68 46.14,38.6 46.03,38.6 45.95,38.68 45.95,38.79 45.87,38.88 45.75,38.88 45.67,38.79 45.67,38.68 45.59,38.6 45.48,38.6 45.4,38.68 45.4,38.79 45.32,38.88 45.21,38.88 45.13,38.79 45.13,38.68 45.05,38.6 44.93,38.6 44.85,38.68 44.85,38.79 44.77,38.88 44.66,38.88 44.58,38.79 44.58,38.68 44.5,38.6 44.38,38.6 44.3,38.68 44.3,38.79 44.22,38.88 44.11,38.88 44.03,38.79 44.03,38.68 43.95,38.6 43.83,38.6 43.75,38.68 43.75,38.79 43.67,38.88 43.56,38.88 43.48,38.79 43.48,38.68 43.4,38.6 43.29,38.6 43.21,38.68 43.21,38.79 43.12,38.88 43.01,38.88 42.93,38.79 42.93,38.68 42.85,38.6 42.74,38.6 42.66,38.68 42.66,38.79 42.58,38.88 42.46,38.88 42.38,38.79 42.38,38.68 42.3,38.6 42.19,38.6 42.11,38.68 42.11,38.79 42.03,38.88 41.72,38.88 39.23,36.39 38.95,36.39 38.69,36.13 38.69,35.79 38.45,35.55 38.11,35.55 36.28,33.72 35.52,33.72 35.07,33.27 35.07,32.78 v2(35.07,32.78)
EMAC[0]_TXCTL: length 20.9
  TOP w0.114: v2(49.67,37.88) 49.6,37.81 R264.1
  TOP w0.12: v2(35.07,31.97) 35.07,31.97 U6.V9
  INT_L3 w0.091: v2(49.67,37.88) 49.67,37.45 49.5,37.27 47.79,37.27 47.47,37.59 47.47,37.98 47.12,38.33 41.51,38.33 39.52,36.34 39.52,35.7 39.41,35.6 39.23,35.6 39.22,35.6 38.93,35.6 38.65,35.32 38.65,34.83 38.56,34.74 38.11,34.74 37.89,34.52 37.89,34.17 37.69,33.97 37.2,33.97 37.04,33.81 37.04,33.42 36.79,33.16 36.47,33.16 36.26,32.96 36.26,32.6 35.65,31.99 35.09,31.99 v2(35.07,31.97)
EMAC[0]_TXD0: length 21.1
  TOP w0.114: R265.1 50.39,37.4 50.76,37.77 v2(50.77,37.77) ; v2(37.3,31.15) 37.07,30.92 U6.U6
  INT_L3 w0.091: v2(37.3,31.15) 37.08,31.38 37.08,33.01 37.22,33.15 37.67,33.15 38.69,34.17 38.69,34.53 38.91,34.75 39.24,34.75 39.49,35 39.49,35.33 39.71,35.55 40.15,35.55 40.54,35.93 40.54,36.11 41.04,36.62 41.04,37.48 41.55,37.99 42.66,37.99 43.07,37.58 43.79,37.58 43.87,37.66 43.87,37.88 43.95,37.96 46.68,37.96 47.58,37.06 48.98,37.06 49.02,37.01 49.54,37.01 49.73,37.2 50.33,37.2 50.77,37.64 v2(50.77,37.77)
EMAC[0]_TXD1: length 21.4
  TOP w0.114: R269.1 v2(51.17,37.71) ; v2(37.38,32.02) 37.07,31.71 U6.V6
  INT_L3 w0.091: v2(37.38,32.02) 37.91,32.55 37.91,32.95 38.91,33.95 39.34,33.95 39.46,34.07 39.46,34.49 39.7,34.74 40.3,34.74 41.09,35.53 41.1,35.53 41.34,35.76 41.34,36.03 42.11,36.8 42.11,36.91 41.76,37.27 41.76,37.38 41.84,37.46 41.95,37.46 42.31,37.11 42.42,37.11 42.61,37.3 44.11,37.3 44.19,37.38 44.19,37.55 44.27,37.63 44.39,37.63 44.47,37.55 44.47,37.38 44.55,37.3 44.66,37.3 44.74,37.38 44.74,37.55 44.82,37.63 44.94,37.63 45.02,37.55 45.02,37.38 45.1,37.3 45.21,37.3 45.29,37.38 45.29,37.55 45.37,37.63 45.49,37.63 45.57,37.55 45.57,37.38 45.65,37.3 45.76,37.3 45.84,37.38 45.84,37.55 45.92,37.63 46.03,37.63 46.11,37.55 46.11,37.38 46.19,37.3 46.96,37.3 47.42,36.84 48.8,36.84 48.87,36.77 49.64,36.77 49.81,36.93 50.71,36.93 51.17,37.4 v2(51.17,37.71)
EMAC[0]_TXD2: length 21.4
  TOP w0.114: R270.1 51.99,37.4 v2(51.6,37.78) ; U6.U7 v2(36.66,31.16)
  INT_L3 w0.091: v2(51.6,37.78) 51.55,37.73 51.55,37.35 50.92,36.72 49.9,36.72 49.72,36.54 48.79,36.54 48.71,36.62 47.03,36.62 46.66,37 46.33,37 46.2,36.87 46.05,36.87 45.93,37 45.78,37 45.65,36.87 45.5,36.87 45.38,37 45.23,37 45.1,36.87 44.96,36.87 44.83,37 44.68,37 44.55,36.87 44.41,36.87 44.28,37 44.13,37 44.01,36.87 43.86,36.87 43.73,37 43.58,37 43.46,36.87 43.31,36.87 43.18,37 42.92,37 40.4,34.48 40.4,34.18 40.17,33.95 40.03,33.95 40.02,33.95 39.71,33.95 39.49,33.73 39.49,33.24 39.38,33.12 39.25,33.12 39.22,33.15 38.91,33.15 37.94,32.18 37.92,32.18 37.79,32.04 37.79,31.71 37.6,31.53 37.6,31.03 37.37,30.8 36.98,30.8 36.66,31.12 v2(36.66,31.16)
EMAC[0]_TXD3: length 21.7
  TOP w0.114: R271.1 52.76,37.29 52.24,37.81 v2(52.06,37.81)
  INT_L3 w0.091: v2(36.29,31.51) 36.29,30.98 36.69,30.57 37.63,30.57 37.86,30.8 37.86,31.33 38.13,31.6 38.42,31.6 38.64,31.82 38.64,32.09 38.93,32.37 39.23,32.37 40.63,33.77 40.63,34.35 41.83,35.55 48.23,35.55 48.27,35.5 50.53,35.5 51.93,36.91 51.93,37.68 v2(52.06,37.81)
EMAC[1]_RXC/PHYAD1: length 9.2
  TOP w0.114: v2(44.89,14.3) 45.2,14.62 45.71,14.62 46.05,14.96 U19.28 ; R315.1 v2(42.46,12.68) 42.14,12.36 42.14,12.36 42.1,12.33 42.1,12.33 41.95,12.18 C197.1 ; R314.2 C197.1 ; C197.1 40.23,12.21 40.23,12.95 R290.2
  INT_L3 w0.091: v2(42.46,12.68) 44.08,14.3 v2(44.89,14.3)
EMAC[1]_RXCTL/PHYAD2: length 5.1
  TOP w0.114: U19.27 46.07,15.36 45.64,14.92 44.98,14.92 44.19,14.13 R316.2 R317.1 42.73,13.74 R289.2
EMAC[1]_RXD0/RXDLY: length 3.9
  TOP w0.114: U19.26 46.1,15.76 46.02,15.84 44.81,15.84 44.44,15.46 R307.2 44.43,15.41 R291.2 43.71,15.41 R308.1
EMAC[1]_RXD1/CFG_MODE0: length 3.5
  TOP w0.114: R292.2 44.44,16.31 R309.2 44.44,16.32 44.95,16.83 45.8,16.83 45.91,16.72 45.91,16.4 46.15,16.16 U19.25
EMAC[1]_RXD2/CFG_MODE1: length 14.4
  TOP w0.114: U19.24 47.29,17.23 46.75,17.77 46.5,17.77 R310.2 45.79,18.33 45.18,18.94 45.18,19.47 v2(44.98,19.67) ; v2(41.72,14.9) 41.72,14.71 41.61,14.59 40.61,14.59 40.3,14.9 R293.2
  INT_L3 w0.091: v2(41.72,14.9) 41.72,15.13 41.88,15.28 41.88,17.79 41.24,18.43 41.24,19.11 41.8,19.67 v2(44.98,19.67)
EMAC[1]_RXD3/CFG_MODE2: length 14.7
  TOP w0.114: v2(46.5,19.29) 46.52,19.27 46.52,18.66 46.86,18.33 R311.2 47.69,17.69 U19.23
  INT_L3 w0.091: v2(46.5,19.29) 45.81,19.98 40.91,19.98 40.73,19.8 40.73,18.1 41.09,17.74 41.09,17.18 41.39,16.88 41.39,16.59 41.31,16.51 41.25,16.51 41.17,16.43 41.17,16.32 41.25,16.24 41.31,16.24 41.39,16.16 41.39,16.04 41.31,15.96 41.25,15.96 41.17,15.88 41.17,15.77 41.25,15.69 41.31,15.69 41.39,15.61 41.39,15.3 41.23,15.14 v2(41.15,15.14)
EMAC[1]_TXC: length 5.5
  TOP w0.114: U6.D5 38.27,20.77 41.67,20.77 R297.1
EMAC[1]_TXCTL: length 3.6
  TOP w0.114: R296.1 42.41,17.99 42.05,18.36 42.05,19.05 41.9,19.19 40.65,19.19 U6.C2
EMAC[1]_TXD0: length 2.4
  TOP w0.12: v8(37.47,19.97) U6.D6
  BOTTOM w0.114: v8(37.47,19.97) 37.62,19.97 R295.1
EMAC[1]_TXD1: length 3.2
  TOP w0.114: R298.1 42.53,17.18 41.34,18.37 40.67,18.37 U6.B2
EMAC[1]_TXD2: length 1.2
  TOP w0.12: U6.C4 38.27,19.97 v8(38.27,20)
  BOTTOM w0.114: R299.1 38.63,19.65 v8(38.27,20)
EMAC[1]_TXD3: length 3.9
  TOP w0.114: R300.1 41.63,19.96 39.92,19.96 39.53,19.57 U6.C3
EMMC_NAND__MMC2_CLK: length 10.2
  TOP w0.114: U6.J7 36.27,24.37 v2(36.67,23.97)
  INT_L3 w0.091: v2(36.67,23.97) 36.67,23.71 36.23,23.27 36.23,22.55 36.24,22.53 36.24,22.22 36.23,22.2 36.23,22.05 36.33,21.95 36.82,21.95 37.04,21.73 37.04,18.87 v3(36.77,18.6)
  SIG_L10 w0.091: v3(36.77,18.6) 36.77,18.53 37.49,17.81 37.49,16.67 v5(37.58,16.57)
  BOTTOM w0.114: R135.1 37.99,16.17 v5(37.58,16.57)
EMMC_NAND__MMC2_CMD: length 9.1
  TOP w0.12: v8(37.47,23.17) U6.H6
  BOTTOM w0.114: v8(37.47,23.17) 37.07,22.77 37.07,19.81 37.3,19.57 37.63,19.57 37.89,19.31 37.89,17.89 39.14,16.64 R132.1
EMMC_NAND__MMC2_DAT0: length 14
  TOP w0.114: v2(39.72,13.91) 39.01,14.61 39.01,15.31 R136.1
  TOP w0.12: v8(39.07,23.97) U6.J4
  INT_L3 w0.091: v8(39.07,23.97) 39.23,23.97 40.25,22.95 40.25,21.43 40.25,21.42 40.25,21.37 39.54,20.67 39.54,14.08 v2(39.72,13.91)
EMMC_NAND__MMC2_DAT1: length 10.6
  INT_L3 w0.091: v2(37.05,24.35) 37.05,23.64 36.83,23.42 36.83,22.96 37.08,22.72 37.08,22.23 37.31,22 37.67,22 37.89,21.78 37.89,18.26 37.48,17.86 37.48,16.52 38.27,15.74 38.27,15.14 v2(38.35,15.05)
EMMC_NAND__MMC2_DAT2: length 13.7
  TOP w0.12: v8(39.07,23.17) U6.H4
  INT_L3 w0.091: v8(39.07,23.17) 39.3,22.94 39.3,22.94 39.46,22.78 39.46,22.19 39.11,21.83 39.11,11.23 v2(38.49,10.6)
EMMC_NAND__MMC2_DAT3: length 11.7
  TOP w0.12: v8(38.27,23.17) U6.H5
  INT_L3 w0.091: v2(38.56,12.4) 38.89,12.73 38.89,21.87 38.7,22.06 38.7,22.72 38.27,23.15 v8(38.27,23.17)
EMMC_NAND__MMC2_DAT4: length 13.2
  TOP w0.114: v2(36.67,24.78) 36.27,25.17 U6.K7
  INT_L3 w0.091: 36.66,24.77 v2(36.67,24.78) ; 36.66,24.77 36.67,24.77 ; 36.66,24.77 36.24,24.35 36.24,23.82 35.47,23.04 35.47,22.24 35.71,22 35.94,22 36.24,21.69 36.24,18.5 36.38,18.37 36.38,17.27 37.89,15.77 37.89,14.58 38.35,14.12 v2(38.35,13.96)
EMMC_NAND__MMC2_DAT5: length 17.2
  TOP w0.114: U6.M7 v2(36.62,26.38)
  INT_L3 w0.091: v2(36.62,26.38) 36.9,26.1 37.63,26.1 37.84,25.89 37.84,25.73 37.86,25.72 37.86,25.41 37.84,25.4 37.84,22.27 38.67,21.44 38.67,13.29 38.22,12.84 38.22,11.5 38.31,11.4 v2(38.47,11.4)
EMMC_NAND__MMC2_DAT6: length 13.5
  TOP w0.114: v2(39.54,13.55) 39.51,13.58 38.85,13.58 R134.1
  TOP w0.12: U6.J5 v8(38.27,23.97)
  INT_L3 w0.091: v8(38.27,23.97) 38.27,23.91 38.62,23.56 39.21,23.56 39.74,23.03 39.74,22.09 39.33,21.67 39.33,13.75 39.54,13.58 v2(39.54,13.55)
EMMC_NAND__MMC2_DAT7: length 19.4
  INT_L3 w0.091: v2(37.1,25.16) 37.07,25.19 36.66,25.19 36.66,25.19 36.33,25.19 36.32,25.19 35.2,25.19 34.69,24.68 34.69,22.22 34.72,22.19 34.72,21.72 34.69,21.69 34.69,21.32 34.82,21.2 35.35,21.2 35.47,21.07 35.47,18.79 36.16,18.1 36.16,17.18 37.56,15.79 37.56,14.52 37.94,14.14 37.94,10.36 v2(38.48,9.82)
EMMC_NAND_MMC2_CLK: length 22.3
  TOP w0.114: U12.M6 v2(26.49,8.71)
  INT_L3 w0.091: v3(39.62,9.82) 39.62,9.76 36.93,7.07 28.39,7.07 26.75,8.71 v2(26.49,8.71)
  SIG_L10 w0.091: v5(37.13,12.81) 37.98,11.96 37.98,10.92 39.08,9.82 v3(39.62,9.82)
  BOTTOM w0.114: v5(37.13,12.81) 37.15,12.84 37.15,13.45 37.83,14.13 R142.2 37.99,14.13 R135.2
EMMC_NAND_MMC2_CMD: length 23.4
  TOP w0.114: U12.M5 v2(26.55,9.19)
  INT_L3 w0.091: v2(26.55,9.19) 26.68,9.19 26.94,8.93 27,8.93 28.52,7.4 28.8,7.4 28.88,7.48 28.88,7.73 28.96,7.81 29.08,7.81 29.16,7.73 29.16,7.48 29.24,7.4 29.35,7.4 29.43,7.48 29.43,7.73 29.51,7.81 29.63,7.81 29.71,7.73 29.71,7.48 29.79,7.4 29.9,7.4 29.98,7.48 29.98,7.73 30.06,7.81 30.17,7.81 30.25,7.73 30.25,7.48 30.33,7.4 30.45,7.4 30.53,7.48 30.53,7.73 30.61,7.81 30.72,7.81 30.8,7.73 30.8,7.48 30.88,7.4 36.85,7.4 39.21,9.77 39.21,9.98 39.71,10.48 v3(39.74,10.48)
  SIG_L10 w0.091: v5(39.44,11.06) 39.74,10.76 v3(39.74,10.48)
  BOTTOM w0.114: R132.2 39.13,14.85 R143.2 39.5,14.13 39.62,14.01 39.62,11.24 v5(39.44,11.06)
EMMC_NAND_MMC2_DAT0: length 18.1
  TOP w0.114: v2(33.49,13.86) 31.46,13.86 31.26,13.65 31.26,13.45 31.36,13.35 32.02,13.35 32.12,13.25 32.12,13.11 32.02,13.01 31.36,13.01 31.26,12.91 31.26,12.56 31.36,12.46 32.66,12.46 32.76,12.36 32.76,12.21 32.66,12.11 32.1,12.11 32,12.01 32,11.87 32.1,11.77 32.66,11.77 32.76,11.67 32.76,11.53 32.66,11.43 32.1,11.43 32,11.33 32,11.19 32.1,11.09 32.66,11.09 32.76,10.98 32.76,10.71 32.46,10.41 U12.A3 ; R136.2 37.52,15.85 R144.2 36.71,15.84 v2(36.6,15.73)
  INT_L3 w0.091: v2(36.6,15.73) 36.56,15.68 36.19,15.68 35.04,14.54 34.27,14.54 34.19,14.46 34.19,14.09 34.11,14.01 34,14.01 33.91,14.09 33.91,14.46 33.83,14.54 33.66,14.54 33.49,14.37 v2(33.49,13.86)
EMMC_NAND_MMC2_DAT1: length 21.7
  TOP w0.114: U12.A4 31.95,9.91 32.2,9.67 32.36,9.67 32.46,9.77 32.46,10.02 32.56,10.12 32.71,10.12 32.81,10.02 32.81,9.77 32.91,9.67 33.05,9.67 33.15,9.77 33.15,10.02 33.25,10.12 33.39,10.12 33.49,10.02 33.49,9.77 33.59,9.67 33.82,9.67 34.03,9.88 34.03,10.7 33.93,10.8 33.29,10.8 33.19,10.9 33.19,11.04 33.29,11.14 33.93,11.14 34.03,11.24 34.03,11.38 33.93,11.49 33.29,11.49 33.14,11.64 33.14,12.41 33.24,12.51 33.9,12.51 34,12.61 34,12.75 33.9,12.85 32.6,12.85 32.5,12.95 32.5,13.37 32.68,13.55 32.85,13.55 32.95,13.45 32.95,13.32 33.05,13.22 33.19,13.22 33.29,13.32 33.29,13.45 33.39,13.55 v2(33.8,13.55) ; 36.71,14.95 37.51,14.95 R133.2 ; 36.71,14.95 v2(37.12,14.54) ; 36.71,14.95 R145.2
  INT_L3 w0.091: v2(37.12,14.54) 37.18,14.59 37.18,15.2 37.1,15.28 36.54,15.28 36.47,15.2 36.47,14.26 36.31,14.11 36.09,14.11 36.01,14.19 36.01,14.77 35.93,14.85 35.82,14.85 35.74,14.77 35.74,14.19 35.66,14.11 34.74,14.11 34.18,13.55 v2(33.8,13.55)
EMMC_NAND_MMC2_DAT2: length 18.3
  TOP w0.114: 36.71,10.6 v2(36.61,10.7) ; 36.71,10.6 R137.2 ; 36.71,10.6 R146.2 ; U12.A5 v2(31.94,9.41)
  INT_L3 w0.091: v2(31.94,9.41) 31.87,9.33 31.45,9.33 31.36,9.24 31.36,8.75 31.54,8.57 32.09,8.57 32.17,8.65 32.17,9 32.25,9.08 32.36,9.08 32.44,9 32.44,8.65 32.52,8.57 32.64,8.57 32.72,8.65 32.72,9 32.8,9.08 32.91,9.08 32.99,9 32.99,8.65 33.07,8.57 33.18,8.57 33.27,8.65 33.27,9 33.35,9.08 33.46,9.08 33.54,9 33.54,8.65 33.62,8.57 33.73,8.57 33.81,8.65 33.81,9 33.89,9.08 34.01,9.08 34.09,9 34.09,8.65 34.17,8.57 34.31,8.57 34.39,8.65 34.39,8.94 34.54,9.08 34.86,9.08 35.04,8.9 35.15,8.9 35.23,8.98 35.23,9.1 35.05,9.28 35.05,9.39 35.13,9.47 35.24,9.47 35.43,9.29 35.54,9.29 35.62,9.37 35.62,9.48 35.44,9.67 35.44,9.78 35.52,9.86 35.63,9.86 35.81,9.68 35.93,9.68 36.01,9.76 36.01,9.87 35.83,10.05 35.83,10.17 35.91,10.25 36.02,10.25 36.2,10.07 36.32,10.07 36.4,10.15 36.4,10.26 36.4,10.26 36.52,10.38 36.77,10.38 37,10.15 37,9.48 37.09,9.39 37.48,9.39 37.57,9.48 37.57,10.74 37.48,10.83 36.75,10.83 v2(36.61,10.7)
EMMC_NAND_MMC2_DAT3: length 20.3
  TOP w0.114: R147.2 36.72,12.3 R138.2
  INT_L3 w0.091: v2(31.04,10.91) 31.04,11.22 31.13,11.32 31.36,11.32 31.45,11.4 31.45,12.05 31.53,12.13 31.64,12.13 31.72,12.05 31.72,11.4 31.8,11.32 31.91,11.32 31.99,11.4 31.99,12.4 32.07,12.48 32.19,12.48 32.27,12.4 32.27,11.4 32.35,11.32 32.46,11.32 32.54,11.4 32.54,12.79 32.62,12.87 32.74,12.87 32.82,12.79 32.82,11.4 32.9,11.32 33.01,11.32 33.09,11.4 33.09,12.79 33.17,12.87 33.29,12.87 33.37,12.79 33.37,11.4 33.45,11.32 33.62,11.32 33.7,11.4 33.7,11.44 33.78,11.52 33.9,11.52 33.98,11.44 33.98,11.4 34.06,11.32 34.17,11.32 34.25,11.4 34.25,11.44 34.33,11.52 34.45,11.52 34.53,11.44 34.53,11.4 34.61,11.32 34.76,11.32 34.88,11.43 34.88,11.54 34.62,11.8 34.62,11.91 34.7,11.99 34.81,11.99 35.07,11.73 35.18,11.73 35.26,11.81 35.26,11.93 35.01,12.18 35.01,12.3 35.09,12.38 35.2,12.38 35.37,12.21 35.52,12.21 35.6,12.29 35.6,13.06 35.68,13.14 35.79,13.14 35.87,13.06 35.87,12.29 35.95,12.21 v2(36.62,12.21)
EMMC_NAND_MMC2_DAT4: length 19.4
  TOP w0.114: R139.2 R148.2
  INT_L3 w0.091: v2(36.62,13.93) 36.77,14.08 37.47,14.08 37.56,13.99 37.56,13.85 37.48,13.77 37.13,13.77 37.05,13.69 37.05,13.58 37.13,13.5 37.48,13.5 37.56,13.42 37.56,13.3 37.48,13.22 37.13,13.22 37.05,13.14 37.05,13.03 37.13,12.95 37.48,12.95 37.56,12.87 37.56,12.75 37.48,12.67 37.13,12.67 37.05,12.59 37.05,12.48 37.13,12.4 37.48,12.4 37.56,12.32 37.56,11.29 37.43,11.16 37.12,11.16 37.02,11.26 37.02,11.67 36.85,11.85 35.83,11.85 34.43,10.45 34.07,10.45 33.99,10.53 33.99,10.93 33.91,11.01 33.8,11.01 33.72,10.93 33.72,10.53 33.64,10.45 33.53,10.45 33.45,10.53 33.45,10.93 33.36,11.01 33.25,11.01 33.17,10.93 33.17,10.53 33.09,10.45 32.98,10.45 32.9,10.53 32.9,10.93 32.82,11.01 32.7,11.01 32.62,10.93 32.62,10.53 32.54,10.45 32.43,10.45 32.35,10.53 32.35,10.93 32.27,11.01 32.15,11.01 32.07,10.93 32.07,10.53 31.99,10.45 31.88,10.45 31.8,10.53 31.8,10.93 31.72,11.01 31.61,11.01 31.53,10.93 31.53,10.53 31.44,10.45 31.08,10.45 v2(31.04,10.41)
EMMC_NAND_MMC2_DAT5: length 14.8
  TOP w0.114: R140.2 36.72,11.4 R149.2
  INT_L3 w0.091: v2(31.04,9.91) 31.32,10.2 31.52,10.2 31.6,10.12 31.6,9.79 31.68,9.71 31.8,9.71 31.88,9.79 31.88,10.12 31.96,10.2 32.37,10.2 32.45,10.12 32.45,9.42 32.53,9.33 32.64,9.33 32.72,9.42 32.72,10.12 32.8,10.2 33.65,10.2 33.73,10.12 33.73,9.42 33.81,9.33 33.92,9.33 34,9.42 34,10.12 34.08,10.2 34.2,10.2 34.28,10.12 34.28,9.42 34.36,9.33 34.47,9.33 34.55,9.42 34.55,10.12 34.63,10.2 34.89,10.2 34.92,10.22 35.03,10.22 35.24,10.01 35.36,10.01 35.44,10.09 35.44,10.2 35.22,10.42 35.22,10.53 35.3,10.61 35.42,10.61 35.63,10.4 35.75,10.4 35.83,10.48 35.83,10.59 35.61,10.81 35.61,10.92 35.69,11 35.81,11 36.02,10.78 36.13,10.78 36.21,10.87 36.21,10.98 36,11.19 36,11.43 36.19,11.62 36.52,11.62 v2(36.62,11.52)
EMMC_NAND_MMC2_DAT6: length 18.6
  TOP w0.114: R134.2 36.72,13.19 R150.2
  INT_L3 w0.091: v2(31.05,9.41) 30.14,10.31 30.14,10.32 29.69,10.76 29.69,10.88 29.83,11.01 29.83,11.12 29.75,11.2 29.63,11.2 29.5,11.07 29.39,11.07 28.91,11.54 28.19,11.54 28.06,11.67 28.06,11.87 28.24,12.05 29.28,12.05 29.79,11.54 30.47,11.54 32.1,13.17 32.29,13.17 32.37,13.25 32.37,13.52 32.45,13.6 32.56,13.6 32.64,13.52 32.64,13.17 32.72,13.09 32.83,13.09 32.92,13.17 32.92,13.52 33,13.6 33.11,13.6 33.19,13.52 33.19,13.25 33.27,13.17 33.69,13.17 33.77,13.09 33.77,12.69 33.85,12.61 33.96,12.61 34.04,12.69 34.04,13.09 34.12,13.17 34.28,13.17 34.87,13.75 35.08,13.75 35.16,13.67 35.16,13.61 35.24,13.53 35.36,13.53 35.44,13.61 35.44,13.67 35.52,13.75 35.63,13.75 35.71,13.67 35.71,13.61 35.79,13.53 35.91,13.53 35.99,13.61 35.99,13.67 36.07,13.75 36.21,13.75 36.62,13.35 v2(36.62,13.07)
EMMC_NAND_MMC2_DAT7: length 12.7
  TOP w0.114: R141.2 36.71,9.82 R151.2
  INT_L3 w0.091: v2(36.61,9.93) 35.79,9.11 35.79,9 35.93,8.86 35.93,8.74 35.85,8.66 35.73,8.66 35.59,8.8 35.48,8.8 35.4,8.72 35.4,8.61 35.54,8.47 35.54,8.36 35.46,8.28 35.34,8.28 35.2,8.42 35.09,8.42 34.94,8.27 34.41,8.27 34.33,8.19 34.33,7.92 34.25,7.84 34.14,7.84 34.06,7.92 34.06,8.19 33.98,8.27 33.86,8.27 33.78,8.19 33.78,7.92 33.7,7.84 33.59,7.84 33.51,7.92 33.51,8.19 33.43,8.27 33.31,8.27 33.23,8.19 33.23,7.92 33.15,7.84 33.04,7.84 32.96,7.92 32.96,8.19 32.88,8.27 32.77,8.27 32.69,8.19 32.69,7.92 32.61,7.84 32.49,7.84 32.41,7.92 32.41,8.19 32.33,8.27 32.22,8.27 32.14,8.19 32.14,7.92 32.06,7.84 31.94,7.84 31.86,7.92 31.86,8.19 31.78,8.27 31.67,8.27 31.59,8.19 31.59,7.92 31.51,7.84 31.39,7.84 31.31,7.92 31.31,8.19 31.04,8.46 v2(31.04,8.91)
EMU0: length 30.2
  TOP w0.114: R154.2 11.08,3.32 10.24,2.49 P1.13 ; U6.G21 v2(24.66,22.36)
  INT_L3 w0.091: v2(24.66,22.36) 24.24,21.95 24.24,21.42 24.02,21.2 23.69,21.2 23.49,20.99 23.49,18.83 22.67,18.02 22.67,15.89 20.94,14.15 20.94,8.64 17.8,5.5 12.44,5.5 10.96,4.03 10.96,3.74 11.06,3.65 v2(11.19,3.65)
  vias: v1(23.49,22.8) v1(24.27,22.8) v2(23.49,22.8) v2(24.27,22.8)
EMU1: length 28.8
  TOP w0.114: U6.D24 v2(22.27,19.97) ; R167.2 9.59,2.99 9.59,1.54 P1.14
  INT_L3 w0.091: v2(10.02,3.54) 12.66,6.18 16.62,6.18 16.68,6.11 16.93,6.11 17,6.18 17.03,6.18 19.45,8.6 19.45,9.49 20.15,10.19 20.15,11.78 19.84,12.09 19.84,13.93 19.84,14.37 21.3,15.84 21.3,16.29 20.79,16.79 20.79,19.03 21.31,19.55 21.69,19.55 22.11,19.97 v2(22.27,19.97)
EMU_RSTN: length 18.5
  TOP w0.114: U5.2 20.57,5.91 19.78,5.91 19.65,6.03 19.65,7.38 20.38,8.11 R57.1 ; C156.1 8.97,3.27 P1.15
  INT_L3 w0.091: v2(21.07,5.93) 20.98,5.93 18.14,3.09 9.64,3.09 9.36,3.37 v2(9.36,3.47)
ETH0_AND_RESETN: length 6.9
  TOP w0.114: v2(53.51,36.44) 53.6,36.34 R276.2 53.53,36.23 U17.13 ; U18.4 53.57,40.69 53.61,40.73 v2(53.79,40.73)
  INT_L3 w0.091: v2(53.79,40.73) 53.79,40.5 53.92,40.37 53.92,36.84 v2(53.51,36.44)
ETH0_AVDD10: length 17.4
  TOP w0.254: U17.9 v2(54.96,32.49) ; v2(54.96,30.49) 54.95,30.49 U17.4 ; U17.47 v2(53.13,27.75)
  INT_L3 w0.254: v2(54.96,30.49) 54.78,30.49 v3(54.5,30.77) ; v3(54.36,32.46) 54.38,32.49 v2(54.96,32.49) ; v3(53.56,27.01) 53.13,27.45 v2(53.13,27.75)
  SIG_L10 w0.254: v5(54.83,33.26) 54.74,33.17 54.74,32.84 54.36,32.46 v3(54.36,32.46) ; v3(54.5,30.77) 54.7,30.57 v5(54.7,30.32) ; v3(53.56,27.01) 53.56,27.62 v5(53.53,27.65)
  BOTTOM w0.114: v5(54.83,33.26) 54.8,33.24 54.8,33.2 C192.1
  BOTTOM w0.254: C190.1 53.03,28.15 v5(53.53,27.65)
  BOTTOM w0.381: C192.1 54.67,33.07 C189.1 54.67,30.13 54.23,29.68 53.31,29.68 53.03,29.41 C190.1 52.86,28.46 52.26,28.46 C193.1 50.69,27.85 L14.1
ETH0_AVDD33: length 14.1
  TOP w0.254: v2(54.63,28.95) 54.28,29.29 U17.1 ; U17.12 54.9,33.69 v2(54.91,33.69)
  INT_L3 w0.091: v3(54.25,29.53) 54.25,29.48 54.63,29.1 v2(54.63,28.95)
  INT_L3 w0.254: v3(55.36,34) 55.06,33.69 v2(54.91,33.69)
  SIG_L10 w0.254: v3(54.25,29.53) 54.63,29.15 v5(54.63,29.12) ; v5(54.47,34.08) 55.28,34.08 v3(55.36,34)
  BOTTOM w0.381: L10.1 51.78,34.58 C180.1 54.34,34.09 ; 54.34,34.09 55.09,34.09 55.36,33.82 55.36,29.83 C178.2 ; 54.34,34.09 C179.2
